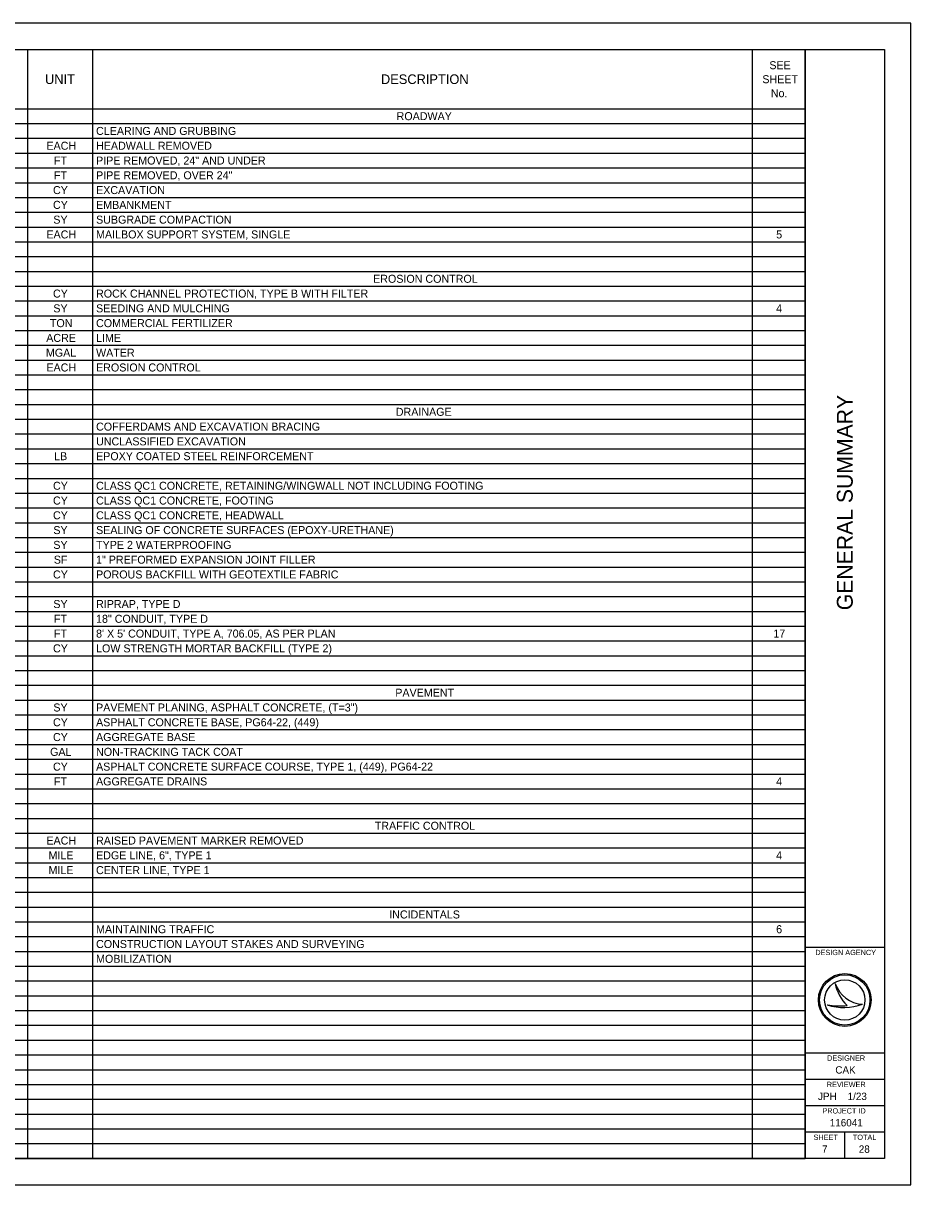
# Model space of a CAD drawing. Extents: x 0 to 34, y 0 to 22.
# Drawn here: x 17.18 to 34, y 0 to 22 of the extents above; entities that cross this region are included whole.
import ezdxf

# ---------------------------------------------------------------- set-up
doc = ezdxf.new("R2010")
doc.units = 0
for name, color, linetype in [('SH_Border', 7, 'Continuous'), ('SH_Cut_Line', 7, 'Continuous'), ('SH_Data', 7, 'Continuous'), ('SH_Text', 7, 'Continuous')]:
    doc.layers.add(name, color=color, linetype=linetype)

msp = doc.modelspace()

# ---------------------------------------------------------------- linework, layer by layer
at = {"layer": 'SH_Border'}
for p, q in [((32, 0.5), (32, 21.5)), ((32, 4.5), (33.5, 4.5)), ((32, 2.5), (33.5, 2.5)), ((32, 2), (33.5, 2)), ((32, 1.5), (33.5, 1.5)), ((32, 1), (33.5, 1))]:
    msp.add_line(p, q, dxfattribs=at)
msp.add_lwpolyline([(1.5, 21.5), (33.5, 21.5), (33.5, 0.5), (1.5, 0.5)], close=True, dxfattribs=at)
at = {"layer": 'SH_Cut_Line'}
msp.add_lwpolyline([(0, 0), (34, 0), (34, 22), (0, 22)], close=True, dxfattribs=at)
at = {"layer": 'SH_Data'}
for p, q in [((32.567, 3.81), (32.567, 3.81)), ((32.417, 3.41), (32.417, 3.41)), ((32.75, 3.5), (32.75, 3.5)), ((33.087, 3.419), (33.087, 3.419)), ((32.75, 0.5), (32.75, 1)), ((32.375, 0.675), (32.375, 0.675))]:
    msp.add_line(p, q, dxfattribs=at)
for radius in [0.5, 0.477, 0.477, 0.382]:
    msp.add_circle((32.75, 3.5), radius, dxfattribs=at)
for centre, radius, start, end in [((33.116, 3.998), 0.58, 198.9257, 198.9319), ((33.347, 3.97), 0.796, 191.6379, 191.6421), ((33.116, 3.998), 0.58, 198.9319, 267.1657), ((33.347, 3.97), 0.796, 191.6421, 226.0947), ((32.739, 4.37), 1.013, 251.4576, 290.0832), ((32.648, 4.654), 1.266, 259.4964, 259.4995), ((32.739, 4.37), 1.013, 251.4527, 251.4576), ((32.648, 4.654), 1.266, 259.4995, 276.6672)]:
    msp.add_arc(centre, radius, start, end, dxfattribs=at)
at = {"layer": 'SH_Text'}
for p, q in [((1.5, 21.5), (32, 21.5)), ((17.261, 21.5), (17.261, 0.5)), ((18.496, 21.5), (18.496, 0.5)), ((30.995, 21.5), (30.995, 0.5)), ((32, 21.5), (32, 0.5)), ((1.5, 20.38), (32, 20.38)), ((1.5, 20.1), (32, 20.1)), ((1.5, 19.82), (32, 19.82)), ((1.5, 19.54), (32, 19.54)), ((1.5, 19.26), (32, 19.26)), ((1.5, 18.98), (32, 18.98)), ((1.5, 18.7), (32, 18.7)), ((1.5, 18.42), (32, 18.42)), ((1.5, 18.14), (32, 18.14)), ((1.5, 17.86), (32, 17.86)), ((1.5, 17.58), (32, 17.58)), ((1.5, 17.3), (32, 17.3)), ((1.5, 17.02), (32, 17.02)), ((1.5, 16.74), (32, 16.74)), ((1.5, 16.46), (32, 16.46)), ((1.5, 16.18), (32, 16.18)), ((1.5, 15.9), (32, 15.9)), ((1.5, 15.62), (32, 15.62)), ((1.5, 15.34), (32, 15.34)), ((1.5, 15.06), (32, 15.06)), ((1.5, 14.78), (32, 14.78)), ((1.5, 14.5), (32, 14.5)), ((1.5, 14.22), (32, 14.22)), ((1.5, 13.94), (32, 13.94)), ((1.5, 13.66), (32, 13.66)), ((1.5, 13.38), (32, 13.38)), ((1.5, 13.1), (32, 13.1)), ((1.5, 12.82), (32, 12.82)), ((1.5, 12.54), (32, 12.54)), ((1.5, 12.26), (32, 12.26)), ((1.5, 11.98), (32, 11.98)), ((1.5, 11.7), (32, 11.7)), ((1.5, 11.42), (32, 11.42)), ((1.5, 11.14), (32, 11.14)), ((1.5, 10.86), (32, 10.86)), ((1.5, 10.58), (32, 10.58)), ((1.5, 10.3), (32, 10.3)), ((1.5, 10.02), (32, 10.02)), ((1.5, 9.74), (32, 9.74)), ((1.5, 9.46), (32, 9.46)), ((1.5, 9.18), (32, 9.18)), ((1.5, 8.9), (32, 8.9)), ((1.5, 8.62), (32, 8.62)), ((1.5, 8.34), (32, 8.34)), ((1.5, 8.06), (32, 8.06)), ((1.5, 7.78), (32, 7.78)), ((1.5, 7.5), (32, 7.5)), ((1.5, 7.22), (32, 7.22)), ((1.5, 6.94), (32, 6.94)), ((1.5, 6.66), (32, 6.66)), ((1.5, 6.38), (32, 6.38)), ((1.5, 6.1), (32, 6.1)), ((1.5, 5.82), (32, 5.82)), ((1.5, 5.54), (32, 5.54)), ((1.5, 5.26), (32, 5.26)), ((1.5, 4.98), (32, 4.98)), ((1.5, 4.7), (32, 4.7)), ((1.5, 4.42), (32, 4.42)), ((1.5, 4.14), (32, 4.14)), ((1.5, 3.86), (32, 3.86)), ((1.5, 3.58), (32, 3.58)), ((1.5, 3.3), (32, 3.3)), ((1.5, 3.02), (32, 3.02)), ((1.5, 2.74), (32, 2.74)), ((1.5, 2.46), (32, 2.46)), ((1.5, 2.18), (32, 2.18)), ((1.5, 1.9), (32, 1.9)), ((1.5, 1.62), (32, 1.62)), ((1.5, 1.34), (32, 1.34)), ((1.5, 1.06), (32, 1.06)), ((1.5, 0.78), (32, 0.78)), ((1.5, 0.5), (32, 0.5))]:
    msp.add_line(p, q, dxfattribs=at)

# ---------------------------------------------------------------- texts
at = {"layer": 'SH_Data'}
msp.add_text('GENERAL SUMMARY', height=0.3, rotation=90, dxfattribs=at).set_placement((32.9, 10.882))
for s, height, p in [('DESIGN AGENCY', 0.1, (32.191, 4.35)), ('DESIGNER', 0.1, (32.414, 2.35)), ('CAK', 0.14, (32.57, 2.105)), ('REVIEWER', 0.1, (32.409, 1.85)), ('JPH    1/23', 0.14, (32.242, 1.605)), ('PROJECT ID', 0.1, (32.325, 1.35)), ('116041', 0.14, (32.465, 1.105)), ('SHEET', 0.1, (32.158, 0.85)), ('TOTAL', 0.1, (32.903, 0.85)), ('7', 0.14, (32.318, 0.605)), ('28', 0.14, (33.015, 0.605))]:
    msp.add_text(s, height=height, dxfattribs=at).set_placement(p)
at = {"layer": 'SH_Text'}
for s, height, p in [('SEE ', 0.1515, (31.32, 21.129)), ('UNIT', 0.1818, (17.595, 20.849)), ('DESCRIPTION', 0.18184, (23.96, 20.849)), ('SHEET ', 0.1515, (31.187, 20.864)), ('No.', 0.1515, (31.348, 20.599)), ('ROADWAY', 0.1515, (24.257, 20.164)), ('CLEARING AND GRUBBING', 0.15153, (18.562, 19.884)), ('EACH', 0.1515, (17.621, 19.604)), ('HEADWALL REMOVED', 0.15153, (18.562, 19.604)), ('FT', 0.1515, (17.764, 19.324)), ('PIPE REMOVED, 24" AND UNDER', 0.15153, (18.562, 19.324)), ('FT', 0.1515, (17.764, 19.044)), ('PIPE REMOVED, OVER 24"', 0.15153, (18.562, 19.044)), ('CY', 0.1515, (17.746, 18.764)), ('EXCAVATION', 0.1515, (18.562, 18.764)), ('CY', 0.1515, (17.746, 18.484)), ('EMBANKMENT', 0.1515, (18.562, 18.484)), ('SY', 0.1515, (17.752, 18.204)), ('SUBGRADE COMPACTION', 0.15153, (18.562, 18.204)), ('EACH', 0.1515, (17.621, 17.924)), ('MAILBOX SUPPORT SYSTEM, SINGLE', 0.15153, (18.562, 17.924)), ('5', 0.152, (31.449, 17.924)), ('EROSION CONTROL', 0.15153, (23.812, 17.084)), ('CY', 0.1515, (17.746, 16.804)), ('ROCK CHANNEL PROTECTION, TYPE B WITH FILTER', 0.15153, (18.562, 16.804)), ('SY', 0.1515, (17.752, 16.524)), ('SEEDING AND MULCHING', 0.15153, (18.562, 16.524)), ('4', 0.152, (31.449, 16.524)), ('TON', 0.1515, (17.687, 16.244)), ('COMMERCIAL FERTILIZER', 0.15153, (18.562, 16.244)), ('ACRE', 0.1515, (17.618, 15.964)), ('LIME', 0.1515, (18.562, 15.964)), ('MGAL', 0.1515, (17.612, 15.684)), ('WATER', 0.1515, (18.562, 15.684)), ('EACH', 0.1515, (17.621, 15.404)), ('EROSION CONTROL', 0.15153, (18.562, 15.404)), ('DRAINAGE', 0.1515, (24.242, 14.564)), ('COFFERDAMS AND EXCAVATION BRACING', 0.15153, (18.562, 14.284)), ('UNCLASSIFIED EXCAVATION', 0.15153, (18.562, 14.004)), ('LB', 0.1515, (17.767, 13.724)), ('EPOXY COATED STEEL REINFORCEMENT', 0.15153, (18.562, 13.724)), ('CY', 0.1515, (17.746, 13.164)), ('CLASS QC1 CONCRETE, RETAINING/WINGWALL NOT INCLUDING FOOTING', 0.15153, (18.562, 13.164)), ('CY', 0.1515, (17.746, 12.884)), ('CLASS QC1 CONCRETE, FOOTING', 0.15153, (18.562, 12.884)), ('CY', 0.1515, (17.746, 12.604)), ('CLASS QC1 CONCRETE, HEADWALL', 0.15153, (18.562, 12.604)), ('SY', 0.1515, (17.752, 12.324)), ('SEALING OF CONCRETE SURFACES (EPOXY-URETHANE)', 0.15153, (18.562, 12.324)), ('SY', 0.1515, (17.752, 12.044)), ('TYPE 2 WATERPROOFING', 0.15153, (18.562, 12.044)), ('SF', 0.1515, (17.761, 11.764)), ('1" PREFORMED EXPANSION JOINT FILLER', 0.15153, (18.562, 11.764)), ('CY', 0.1515, (17.746, 11.484)), ('POROUS BACKFILL WITH GEOTEXTILE FABRIC', 0.15153, (18.562, 11.484)), ('SY', 0.1515, (17.752, 10.924)), ('RIPRAP, TYPE D', 0.15153, (18.562, 10.924)), ('FT', 0.1515, (17.764, 10.644)), ('18" CONDUIT, TYPE D', 0.15153, (18.562, 10.644)), ('FT', 0.1515, (17.764, 10.364)), ("8' X 5' CONDUIT, TYPE A, 706.05, AS PER PLAN", 0.15153, (18.562, 10.364)), ('17', 0.1515, (31.396, 10.364)), ('CY', 0.1515, (17.746, 10.084)), ('LOW STRENGTH MORTAR BACKFILL (TYPE 2)', 0.15153, (18.562, 10.084)), ('PAVEMENT', 0.1515, (24.232, 9.244)), ('SY', 0.1515, (17.752, 8.964)), ('PAVEMENT PLANING, ASPHALT CONCRETE, (T=3")', 0.15153, (18.562, 8.964)), ('CY', 0.1515, (17.746, 8.684)), ('ASPHALT CONCRETE BASE, PG64-22, (449)', 0.15153, (18.562, 8.684)), ('CY', 0.1515, (17.746, 8.404)), ('AGGREGATE BASE', 0.15153, (18.562, 8.404)), ('GAL', 0.1515, (17.691, 8.124)), ('NON-TRACKING TACK COAT', 0.15153, (18.562, 8.124)), ('CY', 0.1515, (17.746, 7.844)), ('ASPHALT CONCRETE SURFACE COURSE, TYPE 1, (449), PG64-22', 0.15153, (18.562, 7.844)), ('FT', 0.1515, (17.764, 7.564)), ('AGGREGATE DRAINS', 0.15153, (18.562, 7.564)), ('4', 0.152, (31.449, 7.564)), ('TRAFFIC CONTROL', 0.15153, (23.843, 6.724)), ('EACH', 0.1515, (17.621, 6.444)), ('RAISED PAVEMENT MARKER REMOVED', 0.15153, (18.562, 6.444)), ('MILE', 0.1515, (17.661, 6.164)), ('EDGE LINE, 6", TYPE 1', 0.15153, (18.562, 6.164)), ('4', 0.152, (31.449, 6.164)), ('MILE', 0.1515, (17.661, 5.884)), ('CENTER LINE, TYPE 1', 0.15153, (18.562, 5.884)), ('INCIDENTALS', 0.15153, (24.117, 5.044)), ('MAINTAINING TRAFFIC', 0.15153, (18.562, 4.764)), ('6', 0.152, (31.449, 4.764)), ('CONSTRUCTION LAYOUT STAKES AND SURVEYING', 0.15153, (18.562, 4.484)), ('MOBILIZATION', 0.15153, (18.562, 4.204))]:
    msp.add_text(s, height=height, dxfattribs=at).set_placement(p)

doc.saveas('drawing.dxf')
